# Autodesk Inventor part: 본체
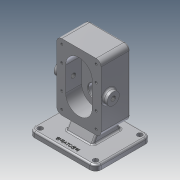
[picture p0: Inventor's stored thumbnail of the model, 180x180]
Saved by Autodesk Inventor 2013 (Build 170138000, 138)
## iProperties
Created: 2020-04
Part Number: 본체
Material: 알루미늄 6061
Document SubType Name: Modeling
Designer: CADCOM
Density: 1 g/cm^3
Author: CADCOM
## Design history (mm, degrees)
sketch "스케치1"
  geometry: L1 (50, 60)-(-50, 60); L2 (-50, 60)-(-50, -60); L3 (-50, -60)-(50, -60); L4 (50, -60)-(50, 60); L5 (50, 60)-(-50, -60); L6 (-50, 60)-(50, -60); 1 further point
  constraints: 12 end point, 2 midpoint, 2 parallel, 1 horizontal, 1 perpendicular
  dimensions: "d0" = 100 distance of L3.end L2.end; "d1" = 120 distance of L2.end L1.end
extrude "돌출1" new body sketch "스케치1" distance "d2" = 10; taper "d3" = 0 deg
fillet "모깎기1" dims "d4" = 10
sketch "스케치2"
  geometry: A1 r 10 centre (-40, -50) between (-50, -50) and (-40, -60) reference; A2 r 10 centre (40, -50) between (40, -60) and (50, -50) reference; A3 r 10 centre (40, 50) between (50, 50) and (40, 60) reference; A4 r 10 centre (-40, 50) between (-40, 60) and (-50, 50) reference; 5 further points
  constraints: 4 coincident
hole "구멍1" sketch "스케치2" at (-40, 50), (40, 50), (40, -50), (-40, -50) diameter "d5" = 9; stored, may be unused: countersink angle "d9" = 90 deg, drill point angle "d11" = 118 deg; dims "d6" = 6, "d7" = 4, "d8" = 2, "d10" = 8
node "작업 평면1"
sketch "스케치3"
  geometry: L1 (20, -40)-(-33, -40); L2 (-33, -40)-(-33, 40); L3 (-33, 40)-(20, 40); L4 (20, 40)-(20, -40); L5 (-40, -60)-(40, -60) reference; L6 (40, 60)-(-40, 60) reference; L7 (-50, 50)-(-50, -50) reference; L8 (20, 0)-(-33, 0); 1 further point
  constraints: 10 end point, 2 midpoint, 2 parallel, 1 horizontal, 1 horizontal alignment, 1 perpendicular
  dimensions: "d13" = 53 distance of L2.end L3.end; "d14" = 80 distance of L1.end L2.end; "d15" = 70 distance between parallel lines of L7 L4
extrude "돌출2" join sketch "스케치3" distance "d16" = 120; taper "d17" = 0 deg
sketch "스케치4"
  geometry: L1 (50, 0)-(-50, 0) reference; L2 (-50, 0)-(-50, 10) reference; L3 (-50, 10)-(50, 10) reference; L4 (50, 10)-(50, 0) reference; L5 (-20, 30)-(-20, 150) reference; L6 (-20, 150)-(33, 150) reference; L7 (33, 150)-(33, 30) reference; L8 (33, 30)-(-20, 30) reference; L9 (21.453, 30)-(33, 10); L10 (-8.453, 30)-(-20, 10); L11 (-8.453, 30)-(21.453, 30); L12 (33, 10)-(-20, 10); 1 further point
  constraints: 8 end point, 4 point on line, 2 collinear
  dimensions: "d18" = 17 distance of L3.end L9.end; "d19" = 60 deg angle of L3 L9; "d20" = 53 distance of L9.end L10.end; "d21" = 60 deg angle of L3 L10
extrude "돌출3" join sketch "스케치4" stored distance "d22" = 48; taper "d23" = 0 deg
fillet "모깎기2" dims "d24" = 9
sketch "스케치5"
  geometry: A1 r 9 centre (0, 9) between (-9, 9) and (0, 0) reference; A2 r 9 centre (62, 9) between (62, 0) and (71, 9) reference; A3 r 9 centre (62, 111) between (71, 111) and (62, 120) reference; A4 r 9 centre (0, 111) between (0, 120) and (-9, 111) reference; 9 further points
  constraints: 4 coincident, 4 vertical alignment, 2 horizontal alignment
  dimensions: "d25" = 29 distance of point (0, 82) point (0, 111); "d27" = 44 distance of point (0, 38) point (0, 82)
hole "구멍2" sketch "스케치5" at (0, 111), (62, 111), (62, 9), (0, 9), (0, 38), (62, 38), (62, 82), (0, 82) diameter "d28" = 4.134; stored, may be unused: countersink angle "d32" = 90 deg, drill point angle "d34" = 118 deg; dims "d29" = 10, "d30" = 4, "d31" = 2, "d33" = 12
sketch "스케치6"
  geometry: L1 (62, 0)-(0, 0) reference; L2 (0, 120)-(62, 120) reference; L3 (-9, 9)-(-9, 111) reference; L4 (7, 82)-(7, 38); L5 (55, 82)-(55, 38); L6 (7, 60)-(55, 60); A1 r 24 centre (31, 38) between (7, 38) and (55, 38); A2 r 24 centre (31, 82) between (55, 82) and (7, 82); 5 further points
  constraints: 6 end point, 6 point on circle, 4 midpoint, 2 centre point, 2 tangent, 2 vertical alignment, 1 parallel
  dimensions: "d36" = 24 radius of A1; "d37" = 92 distance of point (31, 14) point (31, 106); "d38" = 22 distance from line of A2.centre L6; "d39" = 14 distance from line of point (31, 106) L2; "d40" = 24 radius of A2
extrude "돌출4" cut sketch "스케치6" distance "d41" = 29; taper "d42" = 0 deg
sketch "스케치7"
  geometry: C1 r 12.5 at (31, 82); A1 r 24 centre (31, 82) between (55, 82) and (7, 82) reference; 1 further point
  constraints: 1 centre point, 1 coincident
  dimensions: "d43" = 25 diameter of C1
extrude "돌출5" cut sketch "스케치7" distance "d44" = 15; taper "d45" = 0 deg
sketch "스케치9"
  geometry: C1 r 12.5 at (31, 38); A1 r 24 centre (31, 38) between (7, 38) and (55, 38) reference; 1 further point
  constraints: 1 centre point, 1 coincident
  dimensions: "d49" = 25 diameter of C1
extrude "돌출7" cut sketch "스케치9" distance "d50" = 15; taper "d51" = 0 deg
sketch "스케치10"
  geometry: L1 (0, 0)-(0, 102) reference; L2 (0, 0)-(0, 102) reference; L3 (0, 102)-(53, 102) reference; L4 (53, 102)-(53, 0) reference; L5 (53, 0)-(0, 0) reference; L6 (70, -39)-(-30, -39) reference; L7 (-30, -39)-(-30, -29) reference; L8 (-30, -29)-(70, -29) reference; L9 (70, -29)-(70, -39) reference; C1 r 11 at (14, 49.514); 1 further point
  constraints: 1 centre point
  dimensions: "d52" = 22 diameter of C1; "d53" = 14 distance from line of C1.centre L1
extrude "돌출8" join sketch "스케치10" distance "d54" = 8; taper "d55" = 0 deg
sketch "스케치13"
  geometry: C1 r 11 at (0, 0) reference; 2 further points
  constraints: 1 coincident
hole "구멍5" sketch "스케치13" at (0, 0) diameter "d70" = 8.376; stored, may be unused: countersink angle "d74" = 90 deg, drill point angle "d76" = 118 deg; dims "d71" = 30, "d72" = 4, "d73" = 2, "d75" = 30
sketch "스케치14"
  geometry: C1 r 8.5 at (31, 82) reference; C2 r 19 at (31, 82); 1 further point
  constraints: 1 centre point, 1 coincident
  dimensions: "d77" = 38 diameter of C2
extrude "돌출9" join sketch "스케치14" distance "d78" = 17; taper "d79" = 0 deg
sketch "스케치15"
  geometry: C1 r 19 at (0, 0) reference; C2 r 14 at (0, 0); 1 further point
  constraints: 1 centre point, 1 coincident
  dimensions: "d80" = 28 diameter of C2
extrude "돌출10" cut sketch "스케치15" distance "d81" = 7.3; taper "d82" = 0 deg
sketch "스케치16"
  geometry: C1 r 12.5 at (0, 0) reference; C2 r 8.5 at (0, 0); 1 further point
  constraints: 1 centre point, 1 coincident
  dimensions: "d83" = 17 diameter of C2
extrude "돌출11" cut sketch "스케치16" stored distance "d84" = 7.3; taper "d85" = 0 deg
chamfer "모따기1" distance "d86" = 0.7; stored, may be unused: second distance "d87" = 2, angle "d88" = 30 deg
fillet "모깎기3" dims "d89" = 0.5
fillet "모깎기4" dims "d90" = 3
fillet "모깎기5" dims "d91" = 3
fillet "모깎기6" dims "d92" = 3
fillet "모깎기7" dims "d93" = 3
fillet "모깎기8" dims "d94" = 3
chamfer "모따기2" distance "d95" = 1; stored, may be unused: second distance "d96" = 2, angle "d97" = 30 deg
chamfer "모따기3" distance "d98" = 1; stored, may be unused: second distance "d99" = 2, angle "d100" = 30 deg
sketch "스케치17"
  geometry: L1 (40, 60)-(-40, 60) reference; L2 (-50, 50)-(-50, -50) reference; 2 further points
  constraints: 1 other
  dimensions: "d102" = 10 distance from line of L2 point (-40, 0); "d103" = 60 distance from line of L1 point (-40, 0)
feature "엠보싱1" sketch "스케치17" dims "d0" = 100, "d1" = 120, "d104" = 0.5, "d105" = 0
node "솔리드1"
mirror "대칭1"
mirror "대칭2"
node "절단 모서리 투영1"
node "절단 모서리 투영2"
other parameters: "d35" = 24
